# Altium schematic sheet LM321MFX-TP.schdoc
size 127 x 101 mm
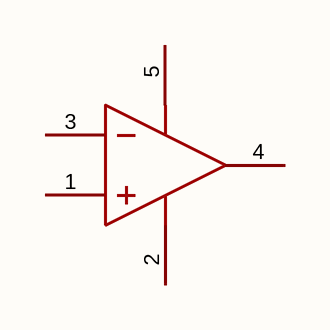
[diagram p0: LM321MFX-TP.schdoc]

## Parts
U?  lm321mfx-tp  [SOT-23-5_L3.0-W1.7-P0.95-LS2.8-BL]  (value not drawn)

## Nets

Not connected (* = marked no-connect by the designer): U? 1(IN+) 2(V-) 3(IN-) 4(OUT) 5(V+)

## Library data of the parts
U? = lm321mfx-tp: 放大器数:1;轨到轨:-;增益带宽积(GBW):1MHz;输入失调电压(Vos):2mV;压摆率(SR):400V/ms;输入偏置电流(Ib):45nA;; Manufacturer: TECH PUBLIC(台舟); AddInBom: yes; ModelId: 0a2a1b8f50944f73965918ad6e5fe167; ModelName: SOT-23-5_L2.9-W1.6-H1.1-LS2.8-P0.95; ModelTransform: 118.60433,114.173,0,90,0,0,0.0005,0.0005,0; Number of Channels: 1; Gain Bandwidth Product: 1MHz; Vos - Input Offset Voltage: 2mV; Ib - Input Bias Current: 45nA; Input Offset Current(Ios): 3nA; Common Mode Rejection Ratio(CMRR): 90dB; Quiescent Current: 100uA; Output Current: 40mA; Single supply: 3V~32V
